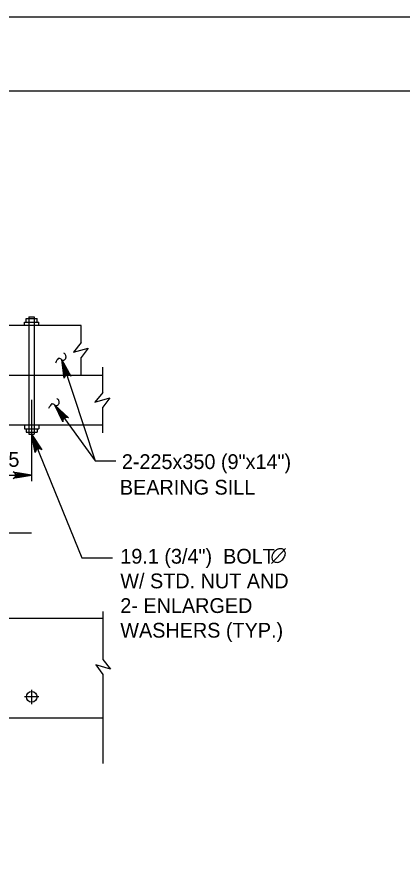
# Model space of a CAD drawing. Extents: x 635440 to 640306, y 296653 to 298484.
# Drawn here: x 640022.7 to 640100.8, y 298265.3 to 298435.5 of the extents above; entities that cross this region are included whole.
import ezdxf

# ---------------------------------------------------------------- set-up
doc = ezdxf.new("R2010")
doc.units = 0
for name, color, linetype in [('2', 7, 'Continuous'), ('3', 7, 'Continuous'), ('4', 7, 'Continuous'), ('5', 7, 'Continuous'), ('PLT-BNDY', 7, 'Continuous')]:
    doc.layers.add(name, color=color, linetype=linetype)

msp = doc.modelspace()

# ---------------------------------------------------------------- linework, layer by layer
at = {"layer": '2'}
msp.add_line((639316.46, 298420.46), (640102.46, 298420.46), dxfattribs=at)
at = {"layer": '3'}
for p, q in [((640024.24, 298373.57), (640027.13, 298373.57)), ((640024.24, 298372.84), (640024.24, 298373.57)), ((640024.6, 298374.29), (640026.77, 298374.29)), ((640024.6, 298373.57), (640024.6, 298374.29)), ((640025.14, 298374.65), (640026.22, 298374.65)), ((640025.14, 298374.65), (640025.14, 298350.86)), ((640026.22, 298374.65), (640026.22, 298350.86)), ((640026.77, 298373.57), (640026.77, 298374.29)), ((640027.13, 298372.84), (640027.13, 298373.57)), ((640035.74, 298372.84), (639882.49, 298372.84)), ((640035.74, 298369.4), (640035.74, 298372.84)), ((640035.74, 298369.4), (640034.16, 298367.45)), ((640034.16, 298367.45), (640037.14, 298368.3)), ((640037.14, 298368.3), (640035.74, 298366.38)), ((640035.74, 298362.75), (640035.74, 298366.38)), ((640040.1, 298359.31), (640040.1, 298364.44)), ((640040.1, 298362.75), (639878.13, 298362.75)), ((640040.1, 298359.31), (640038.52, 298357.36)), ((640038.52, 298357.36), (640041.5, 298358.2)), ((640041.5, 298358.2), (640040.1, 298356.29)), ((640040.1, 298351.08), (640040.1, 298356.29)), ((640040.1, 298352.66), (639878.13, 298352.66)), ((640024.24, 298352.66), (640024.24, 298351.94)), ((640024.24, 298351.94), (640027.13, 298351.94)), ((640024.6, 298351.94), (640024.6, 298351.22)), ((640026.77, 298351.94), (640026.77, 298351.22)), ((640027.13, 298352.66), (640027.13, 298351.94)), ((640024.6, 298351.22), (640026.77, 298351.22)), ((640025.14, 298350.86), (640026.22, 298350.86)), ((640040.1, 298314.88), (640040.1, 298305.15)), ((640040.1, 298313.44), (639878.13, 298313.44)), ((640038.71, 298304.05), (640040.1, 298302.14)), ((640041.69, 298303.2), (640038.71, 298304.05)), ((640040.1, 298305.15), (640041.69, 298303.2)), ((640040.1, 298302.14), (640040.1, 298284.08)), ((640025.68, 298299.02), (640025.68, 298296.13)), ((640027.13, 298297.57), (640024.24, 298297.57)), ((640040.1, 298293.25), (639878.13, 298293.25))]:
    msp.add_line(p, q, dxfattribs=at)
msp.add_circle((640025.69, 298297.58), 1.08, dxfattribs=at)
at = {"layer": '4'}
for p, q in [((640031.79, 298365.94), (640038.57, 298345.45)), ((640025.68, 298357.83), (640025.68, 298341.29)), ((640030.4, 298356.74), (640038.57, 298345.45)), ((640038.57, 298345.45), (640042.74, 298345.45)), ((639959.12, 298342.53), (640025.68, 298342.53)), ((640012.6, 298330.86), (640025.66, 298330.86)), ((640035.83, 298325.79), (640042.06, 298325.79))]:
    msp.add_line(p, q, dxfattribs=at)
for points in [[(640031.79, 298365.94), (640033.63, 298362.62), (640033.35, 298362.83), (640033.06, 298362.9), (640032.81, 298362.86), (640032.59, 298362.74), (640032.4, 298362.52), (640032.3, 298362.19), (640031.79, 298365.94), (640032.4, 298362.52), (640032.59, 298362.74), (640031.79, 298365.94), (640032.81, 298362.86), (640033.06, 298362.9), (640031.79, 298365.94), (640033.35, 298362.83)], [(640030.4, 298356.74), (640033.15, 298354.13), (640032.82, 298354.24), (640032.54, 298354.21), (640032.31, 298354.1), (640032.13, 298353.92), (640032.01, 298353.66), (640032.02, 298353.31), (640030.4, 298356.74), (640032.01, 298353.66), (640032.13, 298353.92), (640030.4, 298356.74), (640032.31, 298354.1), (640032.54, 298354.21), (640030.4, 298356.74), (640032.82, 298354.24)], [(640025.68, 298350.86), (640035.83, 298325.79)], [(640025.68, 298350.86), (640027.73, 298347.66), (640027.44, 298347.86), (640027.15, 298347.9), (640026.9, 298347.85), (640026.69, 298347.71), (640026.51, 298347.48), (640026.43, 298347.14), (640025.68, 298350.86), (640026.51, 298347.48), (640026.69, 298347.71), (640025.68, 298350.86), (640026.9, 298347.85), (640027.15, 298347.9), (640025.68, 298350.86), (640027.44, 298347.86)], [(640025.68, 298342.53), (640021.96, 298341.83), (640022.24, 298342.03), (640022.39, 298342.28), (640022.43, 298342.53), (640022.39, 298342.78), (640022.24, 298343.03), (640021.96, 298343.23), (640025.68, 298342.53), (640022.24, 298343.03), (640022.39, 298342.78), (640025.68, 298342.53), (640022.43, 298342.53), (640022.39, 298342.28), (640025.68, 298342.53), (640022.24, 298342.03)]]:
    msp.add_lwpolyline(points, dxfattribs=at)
for points in [[(640025.68, 298350.86), (640026.56, 298348.03), (640027.02, 298348.21)], [(640022.8, 298343.01), (640022.8, 298342.05), (640025.68, 298342.53)]]:
    msp.add_lwpolyline(points, close=True, dxfattribs=at)
for centre, radius, start, end in [((640031.69, 298366.4), 1.01, 39.8006, 60.652), ((640031.95, 298366.61), 0.677, 14.2351, 39.8006), ((640030.85, 298366.34), 1.81, 5.7096, 14.2351), ((640032.67, 298364.53), 2.27, 153.439, 161.9608), ((640032.46, 298364.64), 2.02, 144.4201, 153.439), ((640034.08, 298363.48), 4.02, 138.3715, 144.4201), ((640031.19, 298366.05), 0.151, 106.7241, 138.3715), ((640031.2, 298366.02), 0.18, 77.4691, 106.7241), ((640030.82, 298364.32), 1.92, 68.5955, 77.4691), ((640031.25, 298365.43), 0.729, 48.0647, 68.5955), ((640032.11, 298366.39), 0.556, 228.0647, 251.6054), ((640032.08, 298366.3), 0.461, 251.6054, 287.1056), ((640032.05, 298366.4), 0.568, 287.1056, 318.9992), ((640031.86, 298366.56), 0.816, 318.9992, 333.439), ((640032.08, 298366.45), 0.571, 333.439, 350.7201), ((640032.07, 298366.46), 0.587, 350.7201, 5.7096), ((640031.07, 298355.43), 2.02, 144.4201, 153.439), ((640032.69, 298354.27), 4.02, 138.3715, 144.4201), ((640029.8, 298356.84), 0.151, 106.7241, 138.3715), ((640029.81, 298356.82), 0.18, 77.4691, 106.7241), ((640029.43, 298355.11), 1.92, 68.5955, 77.4691), ((640029.86, 298356.23), 0.729, 48.0647, 68.5955), ((640030.72, 298357.18), 0.556, 228.0647, 251.6054), ((640030.69, 298357.09), 0.461, 251.6054, 287.1056), ((640030.3, 298357.19), 1.01, 39.8006, 60.652), ((640030.66, 298357.19), 0.568, 287.1056, 318.9992), ((640030.56, 298357.41), 0.677, 14.2351, 39.8006), ((640030.47, 298357.36), 0.816, 318.9992, 333.439), ((640030.69, 298357.25), 0.571, 333.439, 350.7201), ((640029.46, 298357.13), 1.81, 5.7096, 14.2351), ((640030.68, 298357.25), 0.587, 350.7201, 5.7096), ((640031.28, 298355.33), 2.27, 153.439, 161.9608)]:
    msp.add_arc(centre, radius, start, end, dxfattribs=at)
at = {"layer": '5'}
msp.add_line((640074.29, 298324.59), (640077.09, 298327.66), dxfattribs=at)
msp.add_spline([(640076.8, 298327.36), (640076.58, 298327.53), (640076.36, 298327.59), (640076.08, 298327.61), (640075.93, 298327.61), (640075.66, 298327.55), (640075.41, 298327.44), (640075.24, 298327.34), (640074.91, 298327.07), (640074.65, 298326.74), (640074.49, 298326.42), (640074.4, 298326.13), (640074.37, 298325.86), (640074.4, 298325.63), (640074.51, 298325.3), (640074.63, 298325.13), (640074.87, 298324.95), (640075.24, 298324.86), (640075.65, 298324.87), (640076.17, 298325.11), (640076.55, 298325.44), (640076.84, 298325.84), (640077.03, 298326.25), (640077.09, 298326.71), (640077.01, 298327.01), (640076.81, 298327.36)], degree=3, dxfattribs=at)
at = {"layer": 'PLT-BNDY'}
msp.add_lwpolyline([(639276.46, 298435.46), (640117.46, 298435.46), (640117.46, 297841.46), (639276.46, 297841.46)], close=True, dxfattribs=at)

# ---------------------------------------------------------------- texts
at = {"layer": '5'}
for s, height, p in [('175', 3, (640016.51, 298344.22)), ('2-225x350 (9"x14")', 3.0001, (640043.96, 298343.77)), ('BEARING SILL', 3.0001, (640043.56, 298338.58)), ('19.1 (3/4")  BOLT', 3.0001, (640043.65, 298324.59)), ('W/ STD. NUT AND', 3.0001, (640043.65, 298319.59)), ('2- ENLARGED', 3.0001, (640043.65, 298314.59)), ('WASHERS (TYP.)', 3.0001, (640043.65, 298309.59))]:
    msp.add_text(s, height=height, dxfattribs=at).set_placement(p)

doc.saveas('drawing.dxf')
